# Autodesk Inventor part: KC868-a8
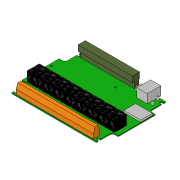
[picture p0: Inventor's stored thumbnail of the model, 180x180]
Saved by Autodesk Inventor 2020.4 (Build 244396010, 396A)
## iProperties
Created: 2022-02
Part Number: KC868-a8
Material: Allgemein
Document SubType Name: Modeling
Mass: 91.7763 g
Surface Area: 573.059 cm^2
Volume: 91.7763 cm^3
Density: 1 g/cm^3
Appearance: Vorgabe
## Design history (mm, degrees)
sketch "Sketch1"
  geometry: L1 (0, 0)-(-74, 0); L2 (-74, 0)-(-74, 28.5); L3 (-74, 28.5)-(-69, 28.5); L4 (-65, 32.5)-(-65, 46.75); L5 (-65, 46.75)-(-62.75, 46.75); L6 (-62.75, 50.25)-(-65, 50.25); L7 (-65, 50.25)-(-65, 53.25); L8 (-65, 53.25)-(0, 53.25); L9 (0, 53.25)-(0, 0); L10 (74, 0)-(74, 28.5); L11 (74, 28.5)-(69, 28.5); L12 (65, 32.5)-(65, 46.75); L13 (65, 46.75)-(62.75, 46.75); L14 (62.75, 50.25)-(65, 50.25); L15 (65, 50.25)-(65, 53.25); L16 (65, 53.25)-(0, 53.25); L17 (0, -53.25)-(0, 0); L18 (65, -53.25)-(0, -53.25); L19 (65, -50.25)-(65, -53.25); L20 (62.75, -50.25)-(65, -50.25); L21 (65, -46.75)-(62.75, -46.75); L22 (65, -32.5)-(65, -46.75); L23 (74, -28.5)-(69, -28.5); L24 (74, 0)-(74, -28.5); L25 (-74, 0)-(-74, -28.5); L26 (-74, -28.5)-(-69, -28.5); L27 (-65, -53.25)-(0, -53.25); L28 (-65, -46.75)-(-62.75, -46.75); L29 (-62.75, -50.25)-(-65, -50.25); L30 (-65, -50.25)-(-65, -53.25); L31 (-65, -32.5)-(-65, -46.75); L32 (-65, 46.75)-(-65, 50.25); C1 r 1.5 at (-70, 13); C2 r 1.5 at (7.5, 33.75); C3 r 1.5 at (34, 5.75); A1 r 4 centre (-69, 32.5) between (-69, 28.5) and (-65, 32.5); A2 r 1.75 centre (-62.75, 48.5) between (-62.75, 46.75) and (-62.75, 50.25); A3 r 4 centre (69, 32.5) between (65, 32.5) and (69, 28.5); A4 r 1.75 centre (62.75, 48.5) between (62.75, 50.25) and (62.75, 46.75); A5 r 1.75 centre (62.75, -48.5) between (62.75, -46.75) and (62.75, -50.25); A6 r 4 centre (69, -32.5) between (69, -28.5) and (65, -32.5); A7 r 4 centre (-69, -32.5) between (-65, -32.5) and (-69, -28.5); A8 r 1.75 centre (-62.75, -48.5) between (-62.75, -50.25) and (-62.75, -46.75)
  constraints: 64 end point, 32 symmetric about line, 16 point on circle, 11 centre point, 8 point on line, 7 perpendicular, 4 tangent, 2 equal radius, 1 horizontal, 1 parallel, 6 other
  dimensions: "d0" = 1.75 radius of A2; "d1" = 4 dimension on A2 L7; "d2" = 130 distance between parallel lines of L15 L7; "d3" = 148 distance between parallel lines of L10 L2; "d4" = 4 radius of A1; "d5" = 57 distance between parallel lines of L26 L3; "d6" = 106.5 distance between parallel lines of L27 L8; "d7" = 3 distance of L6.end L7.end; "d8" = 3 diameter of C1; "d9" = 4 distance from line of C1.centre L2; "d10" = 15.5 distance from line of C1.centre L3; "d11" = 59 distance from line of L18 C3.centre; "d12" = 87 distance from line of L18 C2.centre; "d13" = 40 distance from line of L10 C3.centre; "d14" = 66.5 distance from line of L10 C2.centre
extrude "Extrusion1" new body sketch "Sketch1" distance "d15" = 1.5; taper "d16" = 0 deg
sketch "Sketch2"
  geometry: L1 (-42.25, 1.5)-(-52.25, 1.5); L2 (-52.25, 1.5)-(-52.25, 8.5); L3 (-52.25, 8.5)-(-49.75, 16); L4 (-49.75, 16)-(-44.75, 16); L5 (-44.75, 16)-(-42.25, 8.5); L6 (-42.25, 8.5)-(-42.25, 1.5); L7 (-46.75, 1.5)-(-32.5, 1.5) reference; L8 (-53.25, 1.5)-(-50.25, 1.5) reference; L9 (-53.25, 0)-(-53.25, 1.5) reference; 1 further point
  constraints: 12 end point, 2 equal length, 2 parallel, 1 collinear, 1 perpendicular
  dimensions: "d17" = 1 distance between parallel lines of L2 L9; "d18" = 10 distance of L1.start L1.end; "d19" = 14.5 distance between parallel lines of L1 L4; "d20" = 7 distance of L1.end L2.end; "d21" = 5 distance of L3.end L4.end
extrude "Extrusion2" new body sketch "Sketch2" stored distance "d22" = 119; taper "d23" = 0 deg
sketch "Sketch3"
  geometry: L1 (-52, -9)-(-67, -9); L2 (-67, -9)-(-67, -27.5); L3 (-67, -27.5)-(-52, -27.5); L4 (-52, -27.5)-(-52, -9); L5 (-74, 28.5)-(-74, -28.5) reference; L6 (-74, -28.5)-(-69, -28.5) reference; 1 further point
  constraints: 8 end point, 2 parallel, 1 horizontal, 1 perpendicular
  dimensions: "d24" = 15 distance of L1.start L1.end; "d25" = 18.5 distance of L1.end L2.end; "d26" = 7 distance between parallel lines of L5 L2; "d27" = 1 distance between parallel lines of L6 L3
extrude "Extrusion3" new body sketch "Sketch3" stored distance "d28" = 15.5; taper "d29" = 0 deg
pattern_linear "Rectangular Pattern1" dims "d32" = 17
sketch "Sketch4"
  geometry: L1 (46.25, 1.5)-(53.25, 1.5); L2 (53.25, 1.5)-(53.25, 11); L3 (53.25, 11)-(54.25, 11); L4 (54.25, 11)-(54.25, 20); L5 (54.25, 20)-(43.25, 20); L6 (43.25, 20)-(43.25, 11); L7 (43.25, 11)-(46.25, 11); L8 (46.25, 11)-(46.25, 1.5); L9 (32.5, 1.5)-(46.75, 1.5) reference; L10 (53.25, 0)-(53.25, 1.5) reference; 2 further points
  constraints: 16 end point, 5 perpendicular, 2 collinear, 2 vertical, 1 horizontal, 1 midpoint
  dimensions: "d33" = 1 distance of L2.end L3.end; "d34" = 9 distance of L3.end L4.end; "d35" = 9 distance of L5.end L6.end; "d36" = 9.5 distance of L1.end L2.end; "d37" = 11 distance of L4.end L5.end; "d38" = 7 distance between parallel lines of L8 L2
extrude "Extrusion4" new body sketch "Sketch4" stored distance "d39" = 83.5; taper "d40" = 0 deg
sketch "Sketch5"
  geometry: L1 (-54, 1.5)-(-38, 1.5); L2 (-38, 1.5)-(-38, 15); L3 (-38, 15)-(-54, 15); L4 (-54, 15)-(-54, 1.5); L5 (65, 1.5)-(-65, 1.5) reference; L6 (-65, 0)-(-65, 1.5) reference; 1 further point
  constraints: 8 end point, 2 parallel, 1 collinear, 1 horizontal, 1 perpendicular
  dimensions: "d41" = 11 distance between parallel lines of L4 L6; "d42" = 16 distance of L2.end L3.end; "d43" = 13.5 distance of L1.end L2.end
extrude "Extrusion5" new body sketch "Sketch5" stored distance "d44" = 4; taper "d45" = 0 deg; dims "d46" = 17, "d47" = 0
sketch "Sketch6"
  geometry: L1 (73.7, 24.5)-(47.7, 24.5); L2 (47.7, 24.5)-(47.7, 6.5); L3 (47.7, 6.5)-(73.7, 6.5); L4 (73.7, 6.5)-(73.7, 24.5); L5 (74, 28.5)-(69, 28.5) reference; L6 (74, -28.5)-(74, 28.5) reference; 1 further point
  constraints: 8 end point, 2 parallel, 1 horizontal, 1 perpendicular
  dimensions: "d48" = 26 distance of L1.start L1.end; "d49" = 18 distance of L3.end L1.start; "d50" = 4 distance between parallel lines of L1 L5; "d51" = 0.3 distance between parallel lines of L6 L4
extrude "Extrusion6" new body sketch "Sketch6" stored distance "d52" = 3; taper "d53" = 0 deg
sketch "Sketch7"
  geometry: L1 (27.5, 53.25)-(34.5, 53.25); L2 (34.5, 53.25)-(34.5, 44.25); L3 (34.5, 44.25)-(27.5, 44.25); L4 (27.5, 44.25)-(27.5, 53.25); L5 (65, 53.25)-(-65, 53.25) reference; L6 (38, 36.25)-(38, 57.25) reference; L7 (54, 57.25)-(54, 36.25) reference; L8 (65, 32.5)-(65, 46.75) reference; C1 r 1.25 at (57, 49.25); C2 r 1.25 at (59, 39.25); 1 further point
  constraints: 8 end point, 2 centre point, 2 parallel, 1 collinear, 1 equal radius, 1 horizontal, 1 perpendicular
  dimensions: "d54" = 7 distance of L1.start L1.end; "d55" = 3.5 distance between parallel lines of L6 L2; "d56" = 9 distance of L1.end L2.end; "d57" = 4 distance from line of L5 C1.centre; "d58" = 3 distance from line of L7 C1.centre; "d59" = 2.5 diameter of C1; "d60" = 14 distance from line of L5 C2.centre; "d61" = 6 distance from line of L8 C2.centre
extrude "Extrusion7" new body sketch "Sketch7" stored distance "d62" = 5; taper "d63" = 0 deg
body "Solid1"
body "Solid2"
body "Solid3"
body "Solid4"
body "Solid5"
body "Solid6"
body "Solid7"
other parameters: "G_L" = 1 [user parameter]
